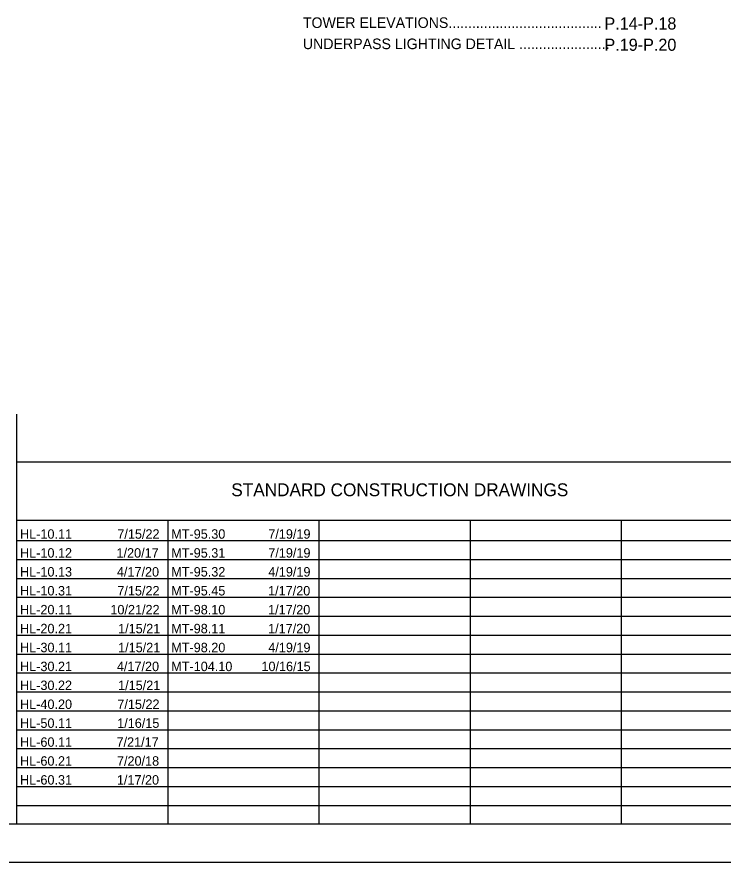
# Model space of a CAD drawing. Extents: x 0 to 51, y -1.2 to 22.
# Drawn here: x 11.25 to 20.59, y 0 to 11.17 of the extents above; entities that cross this region are included whole.
import ezdxf

# ---------------------------------------------------------------- set-up
doc = ezdxf.new("R2010")
doc.units = 0
for name, color, linetype in [('SH_Border', 7, 'Continuous'), ('SH_Cut_Line', 7, 'Continuous'), ('SH_Data', 7, 'Continuous'), ('SH_Text', 7, 'Continuous')]:
    doc.layers.add(name, color=color, linetype=linetype)

msp = doc.modelspace()

# ---------------------------------------------------------------- linework, layer by layer
at = {"layer": 'SH_Border'}
msp.add_lwpolyline([(1.5, 21.5), (33.5, 21.5), (33.5, 0.5), (1.5, 0.5)], close=True, dxfattribs=at)
at = {"layer": 'SH_Cut_Line'}
msp.add_lwpolyline([(0, 0), (34, 0), (34, 22), (0, 22)], close=True, dxfattribs=at)
at = {"layer": 'SH_Text'}
for p, q in [((11.25, 0.5), (11.25, 5.921)), ((11.25, 5.292), (24.7, 5.292)), ((11.25, 0.5), (11.25, 5.292)), ((11.25, 4.521), (24.7, 4.521)), ((13.25, 0.5), (13.25, 4.521)), ((15.25, 0.5), (15.25, 4.521)), ((17.25, 0.5), (17.25, 4.521)), ((19.25, 0.5), (19.25, 4.521)), ((11.25, 4.25), (24.7, 4.25)), ((11.25, 4), (24.7, 4)), ((11.25, 3.75), (24.7, 3.75)), ((11.25, 3.5), (24.7, 3.5)), ((11.25, 3.25), (24.7, 3.25)), ((11.25, 3), (24.7, 3)), ((11.25, 2.75), (24.7, 2.75)), ((11.25, 2.5), (24.7, 2.5)), ((11.25, 2.25), (24.7, 2.25)), ((11.25, 2), (24.7, 2)), ((11.25, 1.75), (24.7, 1.75)), ((11.25, 1.5), (24.7, 1.5)), ((11.25, 1.25), (24.7, 1.25)), ((11.25, 1), (24.7, 1)), ((11.25, 0.75), (24.7, 0.75))]:
    msp.add_line(p, q, dxfattribs=at)

# ---------------------------------------------------------------- texts
at = {"layer": 'SH_Data'}
for s, height, p in [('TOWER ELEVATIONS.......................................', 0.14, (15.033, 11.025)), ('P.14-P.18', 0.16, (19.022, 11.004)), ('UNDERPASS LIGHTING DETAIL .......................', 0.14, (15.033, 10.745)), ('P.19-P.20', 0.16, (19.022, 10.723))]:
    msp.add_text(s, height=height, dxfattribs=at).set_placement(p)
at = {"layer": 'SH_Text'}
for s, height, p in [('STANDARD CONSTRUCTION DRAWINGS', 0.17, (14.086, 4.836)), ('HL-10.11', 0.125, (11.292, 4.274)), ('7/15/22', 0.125, (12.579, 4.274)), ('MT-95.30', 0.125, (13.292, 4.274)), ('7/19/19', 0.125, (14.576, 4.274)), ('HL-10.12', 0.125, (11.292, 4.024)), ('1/20/17', 0.125, (12.568, 4.024)), ('MT-95.31', 0.125, (13.292, 4.024)), ('7/19/19', 0.125, (14.576, 4.024)), ('HL-10.13', 0.125, (11.292, 3.774)), ('4/17/20', 0.125, (12.573, 3.774)), ('MT-95.32', 0.125, (13.292, 3.774)), ('4/19/19', 0.125, (14.576, 3.774)), ('HL-10.31', 0.125, (11.292, 3.524)), ('7/15/22', 0.125, (12.579, 3.524)), ('MT-95.45', 0.125, (13.292, 3.524)), ('1/17/20', 0.125, (14.573, 3.524)), ('HL-20.11', 0.125, (11.292, 3.274)), ('10/21/22', 0.125, (12.487, 3.274)), ('MT-98.10', 0.125, (13.292, 3.274)), ('1/17/20', 0.125, (14.573, 3.274)), ('HL-20.21', 0.125, (11.292, 3.024)), ('1/15/21', 0.125, (12.589, 3.024)), ('MT-98.11', 0.125, (13.292, 3.024)), ('1/17/20', 0.125, (14.573, 3.024)), ('1/15/21', 0.125, (12.589, 2.774)), ('4/19/19', 0.125, (14.576, 2.774)), ('HL-30.11', 0.125, (11.292, 2.774)), ('MT-98.20', 0.125, (13.292, 2.774)), ('HL-30.21', 0.125, (11.292, 2.524)), ('4/17/20', 0.125, (12.573, 2.524)), ('MT-104.10', 0.125, (13.292, 2.524)), ('10/16/15', 0.125, (14.485, 2.524)), ('HL-30.22', 0.125, (11.292, 2.274)), ('1/15/21', 0.125, (12.589, 2.274)), ('HL-40.20', 0.125, (11.292, 2.024)), ('7/15/22', 0.125, (12.579, 2.024)), ('HL-50.11', 0.125, (11.292, 1.774)), ('1/16/15', 0.125, (12.577, 1.774)), ('HL-60.11', 0.125, (11.292, 1.524)), ('7/21/17', 0.125, (12.568, 1.524)), ('HL-60.21', 0.125, (11.292, 1.274)), ('7/20/18', 0.125, (12.574, 1.274)), ('HL-60.31', 0.125, (11.292, 1.024)), ('1/17/20', 0.125, (12.573, 1.024))]:
    msp.add_text(s, height=height, dxfattribs=at).set_placement(p)

doc.saveas('drawing.dxf')
